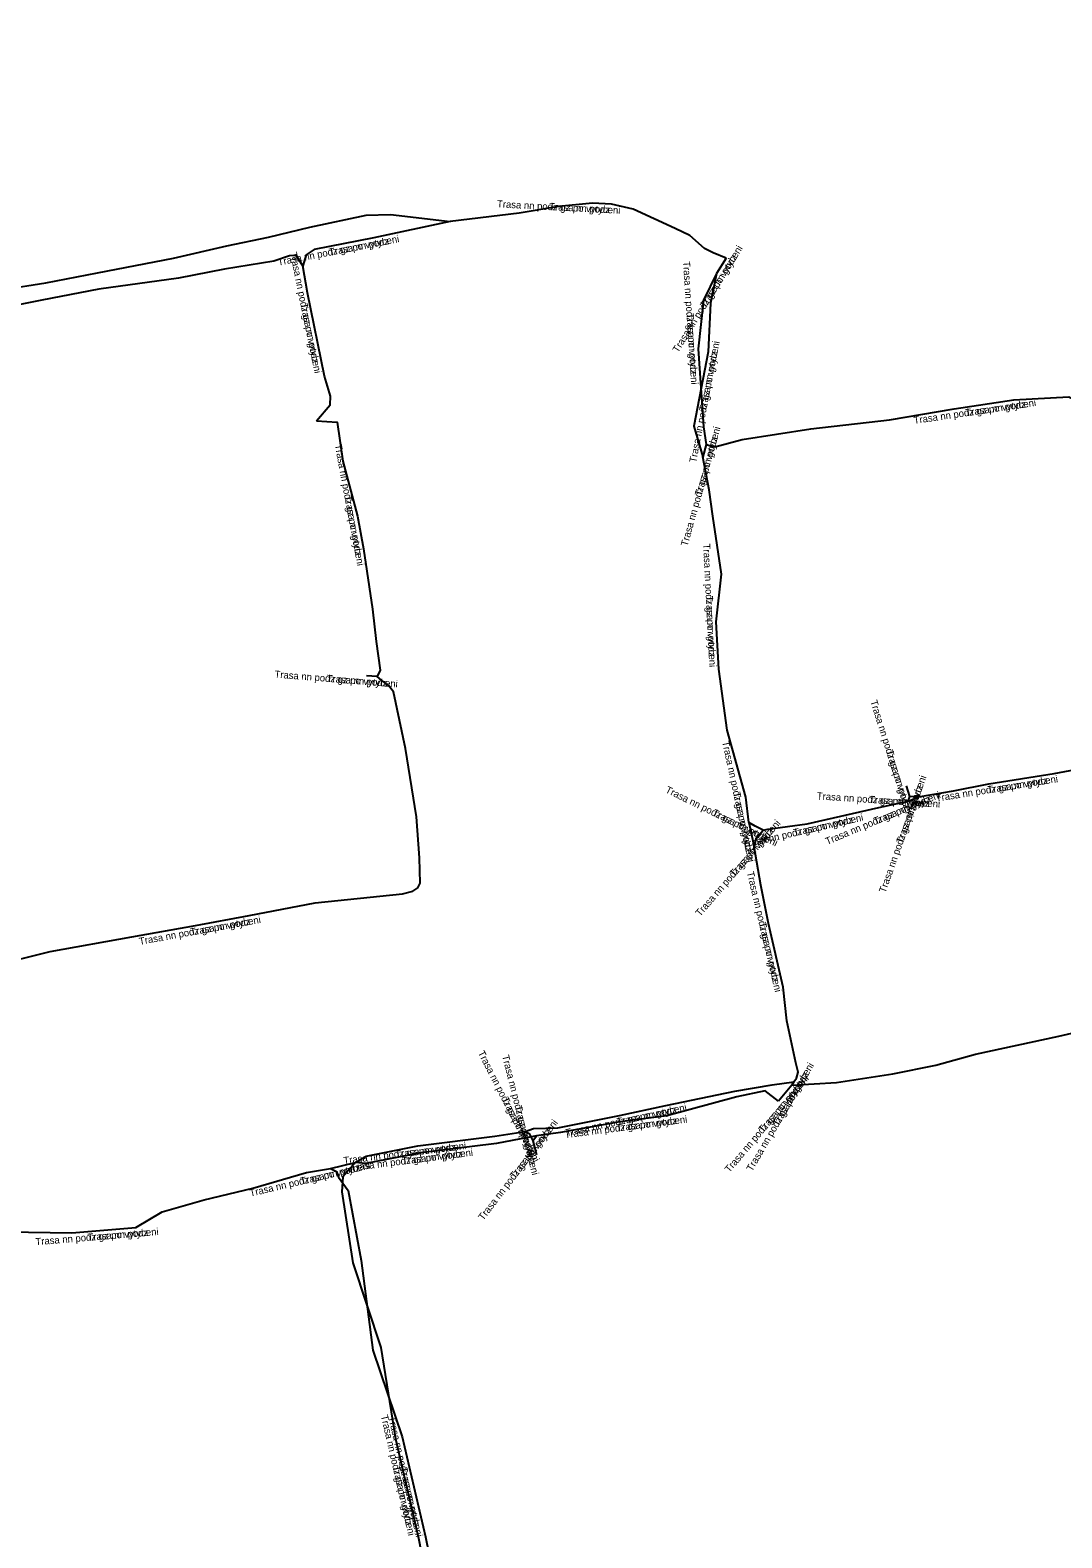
# Model space of a CAD drawing. Extents: x -876384 to -875659, y -1020218 to -1019588.
# Drawn here: x -876029.1 to -875956.5, y -1020036.5 to -1019930.4 of the extents above; entities that cross this region are included whole.
import ezdxf

# ---------------------------------------------------------------- set-up
doc = ezdxf.new("R2010")
doc.units = 0
doc.layers.add('Popiskový text - Ostatní atributy Trasy', color=7, linetype='Continuous')
doc.layers.add('Spojnice NN', color=7, linetype='Continuous')

msp = doc.modelspace()

# ---------------------------------------------------------------- linework, layer by layer
at = {"layer": 'Spojnice NN'}
for points in [[(-876046.32, -1019930.37), (-876047.08, -1019930.93), (-876047.26, -1019931.59), (-876046.92, -1019933.56), (-876045.88, -1019938.99), (-876044.61, -1019943.83), (-876044.42, -1019946.2), (-876043.76, -1019948.18), (-876043.34, -1019949.51), (-876043.03, -1019949.85), (-876042.41, -1019950.34), (-876039.62, -1019949.85), (-876034.17, -1019949.16), (-876030.99, -1019948.63), (-876028.02, -1019948.16), (-876024.37, -1019947.45), (-876019.01, -1019946.41), (-876015.26, -1019945.54), (-876012.33, -1019944.94), (-876009.41, -1019944.24), (-876005.45, -1019943.4), (-876003.75, -1019943.35), (-875999.53, -1019943.84)], [(-876046.32, -1019930.37), (-876047.08, -1019930.93), (-876047.26, -1019931.59), (-876046.92, -1019933.56), (-876045.88, -1019938.99), (-876044.61, -1019943.83), (-876044.42, -1019946.2), (-876043.76, -1019948.18), (-876043.34, -1019949.51), (-876043.03, -1019949.85), (-876042.41, -1019950.34), (-876039.62, -1019949.85), (-876034.17, -1019949.16), (-876030.99, -1019948.63), (-876028.02, -1019948.16), (-876024.37, -1019947.45), (-876019.01, -1019946.41), (-876015.26, -1019945.54), (-876012.33, -1019944.94), (-876009.41, -1019944.24), (-876005.45, -1019943.4), (-876003.75, -1019943.35), (-875999.53, -1019943.84)], [(-875980.11, -1019946.41), (-875981.02, -1019946.05), (-875981.63, -1019945.73), (-875982.67, -1019944.83), (-875983.7, -1019944.32), (-875986.65, -1019942.96), (-875988.18, -1019942.61), (-875989.51, -1019942.54), (-875991.88, -1019942.79), (-875994.69, -1019943.26), (-875999.53, -1019943.84)], [(-875980.11, -1019946.41), (-875981.02, -1019946.05), (-875981.63, -1019945.73), (-875982.67, -1019944.83), (-875983.7, -1019944.32), (-875986.65, -1019942.96), (-875988.18, -1019942.61), (-875989.51, -1019942.54), (-875991.88, -1019942.79), (-875994.69, -1019943.26), (-875999.53, -1019943.84)], [(-875999.53, -1019943.84), (-876004.92, -1019944.98), (-876009.11, -1019945.8), (-876009.67, -1019946.19), (-876009.91, -1019946.97)], [(-875999.53, -1019943.84), (-876004.92, -1019944.98), (-876009.11, -1019945.8), (-876009.67, -1019946.19), (-876009.91, -1019946.97)], [(-876009.91, -1019946.97), (-876010.39, -1019946.23), (-876010.86, -1019946.25), (-876011.96, -1019946.62), (-876015.42, -1019947.19), (-876018.66, -1019947.82), (-876024.27, -1019948.6), (-876028.29, -1019949.37), (-876031.81, -1019950.07), (-876034.22, -1019950.58), (-876039.28, -1019951.74), (-876039.64, -1019952.03), (-876040, -1019952.31), (-876040, -1019952.91), (-876039.65, -1019954.95), (-876038.91, -1019959.38), (-876038.32, -1019963.68), (-876038.31, -1019964.47), (-876038.83, -1019964.88), (-876041.77, -1019965.75), (-876046.71, -1019966.8), (-876049.27, -1019967.19)], [(-876009.91, -1019946.97), (-876010.39, -1019946.23), (-876010.86, -1019946.25), (-876011.96, -1019946.62), (-876015.42, -1019947.19), (-876018.66, -1019947.82), (-876024.27, -1019948.6), (-876028.29, -1019949.37), (-876031.81, -1019950.07), (-876034.22, -1019950.58), (-876039.28, -1019951.74), (-876039.64, -1019952.03), (-876040, -1019952.31), (-876040, -1019952.91), (-876039.65, -1019954.95), (-876038.91, -1019959.38), (-876038.32, -1019963.68), (-876038.31, -1019964.47), (-876038.83, -1019964.88), (-876041.77, -1019965.75), (-876046.71, -1019966.8), (-876049.27, -1019967.19)], [(-876008.96, -1019957.86), (-876007.98, -1019956.75), (-876007.97, -1019956.13), (-876008.39, -1019954.72), (-876009.59, -1019948.87), (-876009.91, -1019946.97)], [(-876008.96, -1019957.86), (-876007.98, -1019956.75), (-876007.97, -1019956.13), (-876008.39, -1019954.72), (-876009.59, -1019948.87), (-876009.91, -1019946.97)], [(-875980.11, -1019946.41), (-875980.79, -1019947.51)], [(-875980.11, -1019946.41), (-875980.79, -1019947.51)], [(-875980.79, -1019947.51), (-875981.2, -1019949.58), (-875981.36, -1019953.02), (-875982.38, -1019958.25), (-875981.74, -1019960.4)], [(-875980.79, -1019947.51), (-875981.2, -1019949.58), (-875981.36, -1019953.02), (-875982.38, -1019958.25), (-875981.74, -1019960.4)], [(-875980.79, -1019947.51), (-875981.7, -1019949.37), (-875982.08, -1019952.81), (-875981.71, -1019958.3), (-875981.5, -1019959.54)], [(-875980.79, -1019947.51), (-875981.7, -1019949.37), (-875982.08, -1019952.81), (-875981.71, -1019958.3), (-875981.5, -1019959.54)], [(-875981.5, -1019959.54), (-875980.91, -1019959.71), (-875978.98, -1019959.19), (-875974.14, -1019958.44), (-875968.61, -1019957.8), (-875964.04, -1019957.02), (-875959.85, -1019956.4), (-875955.98, -1019956.19), (-875954.28, -1019957), (-875950.88, -1019959.65), (-875949.21, -1019960.94), (-875946.66, -1019963.08), (-875946.09, -1019963.7), (-875943.8, -1019965.43), (-875942.97, -1019965.54), (-875941.85, -1019965.97)], [(-875981.5, -1019959.54), (-875980.91, -1019959.71), (-875978.98, -1019959.19), (-875974.14, -1019958.44), (-875968.61, -1019957.8), (-875964.04, -1019957.02), (-875959.85, -1019956.4), (-875955.98, -1019956.19), (-875954.28, -1019957), (-875950.88, -1019959.65), (-875949.21, -1019960.94), (-875946.66, -1019963.08), (-875946.09, -1019963.7), (-875943.8, -1019965.43), (-875942.97, -1019965.54), (-875941.85, -1019965.97)], [(-876008.96, -1019957.86), (-876007.49, -1019957.97), (-876007.09, -1019960.71), (-876006.07, -1019964.57), (-876005.64, -1019966.87), (-876005.01, -1019971.13), (-876004.75, -1019973.39), (-876004.46, -1019975.42), (-876004.68, -1019975.87)], [(-876008.96, -1019957.86), (-876007.49, -1019957.97), (-876007.09, -1019960.71), (-876006.07, -1019964.57), (-876005.64, -1019966.87), (-876005.01, -1019971.13), (-876004.75, -1019973.39), (-876004.46, -1019975.42), (-876004.68, -1019975.87)], [(-875981.5, -1019959.54), (-875981.74, -1019960.4)], [(-875981.5, -1019959.54), (-875981.74, -1019960.4)], [(-875978.5, -1019986.14), (-875978.73, -1019984.36), (-875980.03, -1019979.65), (-875980.63, -1019975.35), (-875980.8, -1019972.01), (-875980.43, -1019968.65), (-875981.04, -1019964.59), (-875981.31, -1019962.72), (-875981.74, -1019960.4)], [(-875978.5, -1019986.14), (-875978.73, -1019984.36), (-875980.03, -1019979.65), (-875980.63, -1019975.35), (-875980.8, -1019972.01), (-875980.43, -1019968.65), (-875981.04, -1019964.59), (-875981.31, -1019962.72), (-875981.74, -1019960.4)], [(-876043.1, -1019998.12), (-876042.68, -1019998.01), (-876040.94, -1019997.81), (-876037.72, -1019997.37), (-876032.34, -1019996.37), (-876027.71, -1019995.21), (-876021.96, -1019994.19), (-876017.47, -1019993.38), (-876013.69, -1019992.69), (-876009.04, -1019991.79), (-876002.9, -1019991.16), (-876002.17, -1019990.97), (-876001.82, -1019990.74), (-876001.65, -1019990.42), (-876001.69, -1019988.63), (-876001.9, -1019985.73), (-876002.68, -1019980.94), (-876003.52, -1019976.94), (-876003.88, -1019976.49), (-876004.36, -1019976.15), (-876004.68, -1019975.87)], [(-876043.1, -1019998.12), (-876042.68, -1019998.01), (-876040.94, -1019997.81), (-876037.72, -1019997.37), (-876032.34, -1019996.37), (-876027.71, -1019995.21), (-876021.96, -1019994.19), (-876017.47, -1019993.38), (-876013.69, -1019992.69), (-876009.04, -1019991.79), (-876002.9, -1019991.16), (-876002.17, -1019990.97), (-876001.82, -1019990.74), (-876001.65, -1019990.42), (-876001.69, -1019988.63), (-876001.9, -1019985.73), (-876002.68, -1019980.94), (-876003.52, -1019976.94), (-876003.88, -1019976.49), (-876004.36, -1019976.15), (-876004.68, -1019975.87)], [(-876004.68, -1019975.87), (-876005.43, -1019975.81)], [(-876004.68, -1019975.87), (-876005.43, -1019975.81)], [(-875966.57, -1019984.34), (-875964.09, -1019983.91), (-875961.6, -1019983.42), (-875957.01, -1019982.68), (-875952.25, -1019981.79), (-875950.75, -1019981.55)], [(-875966.57, -1019984.34), (-875964.09, -1019983.91), (-875961.6, -1019983.42), (-875957.01, -1019982.68), (-875952.25, -1019981.79), (-875950.75, -1019981.55)], [(-875967.17, -1019984.3), (-875967.4, -1019983.57)], [(-875967.17, -1019984.3), (-875967.4, -1019983.57)], [(-875967.29, -1019984.64), (-875967.17, -1019984.3)], [(-875967.29, -1019984.64), (-875967.17, -1019984.3)], [(-875967.29, -1019984.64), (-875966.57, -1019984.34)], [(-875967.29, -1019984.64), (-875966.57, -1019984.34)], [(-875966.57, -1019984.34), (-875967.17, -1019984.3)], [(-875966.57, -1019984.34), (-875967.17, -1019984.3)], [(-875977.5, -1019986.68), (-875977.16, -1019986.62), (-875974.39, -1019986.24), (-875969.36, -1019985.09), (-875967.29, -1019984.64)], [(-875977.5, -1019986.68), (-875977.16, -1019986.62), (-875974.39, -1019986.24), (-875969.36, -1019985.09), (-875967.29, -1019984.64)], [(-875978.5, -1019986.14), (-875978.13, -1019987.86)], [(-875977.5, -1019986.68), (-875978.07, -1019986.4), (-875978.5, -1019986.14)], [(-875978.5, -1019986.14), (-875978.13, -1019987.86)], [(-875977.5, -1019986.68), (-875978.07, -1019986.4), (-875978.5, -1019986.14)], [(-875978.13, -1019987.86), (-875977.96, -1019987.21), (-875977.5, -1019986.68)], [(-875978.13, -1019987.86), (-875977.96, -1019987.21), (-875977.5, -1019986.68)], [(-875975.33, -1020004.39), (-875975.14, -1020004.14), (-875975.03, -1020003.71), (-875975.2, -1020003.05), (-875975.82, -1020000.1), (-875976.08, -1019997.73), (-875977.13, -1019993.26), (-875977.66, -1019990.56), (-875978.13, -1019987.86)], [(-875975.33, -1020004.39), (-875975.14, -1020004.14), (-875975.03, -1020003.71), (-875975.2, -1020003.05), (-875975.82, -1020000.1), (-875976.08, -1019997.73), (-875977.13, -1019993.26), (-875977.66, -1019990.56), (-875978.13, -1019987.86)], [(-875975.47, -1020004.63), (-875972.34, -1020004.43), (-875968.36, -1020003.82), (-875965.34, -1020003.23), (-875962.55, -1020002.44), (-875956.68, -1020001.19), (-875952.92, -1020000.31), (-875949.46, -1019999.58), (-875945.94, -1019998.74), (-875940.82, -1019997.67), (-875936.58, -1019996.62), (-875933.3, -1019996.1), (-875928.99, -1019995.29), (-875926.52, -1019994.63), (-875924.66, -1019994.27), (-875923.64, -1019994.19)], [(-875975.47, -1020004.63), (-875972.34, -1020004.43), (-875968.36, -1020003.82), (-875965.34, -1020003.23), (-875962.55, -1020002.44), (-875956.68, -1020001.19), (-875952.92, -1020000.31), (-875949.46, -1019999.58), (-875945.94, -1019998.74), (-875940.82, -1019997.67), (-875936.58, -1019996.62), (-875933.3, -1019996.1), (-875928.99, -1019995.29), (-875926.52, -1019994.63), (-875924.66, -1019994.27), (-875923.64, -1019994.19)], [(-875994.26, -1020007.89), (-875993.66, -1020007.68), (-875991.95, -1020007.63), (-875987.62, -1020006.77), (-875984.36, -1020006.07), (-875979.49, -1020005.04), (-875976.87, -1020004.6), (-875975.33, -1020004.39)], [(-875994.26, -1020007.89), (-875993.66, -1020007.68), (-875991.95, -1020007.63), (-875987.62, -1020006.77), (-875984.36, -1020006.07), (-875979.49, -1020005.04), (-875976.87, -1020004.6), (-875975.33, -1020004.39)], [(-875975.47, -1020004.63), (-875976.42, -1020005.75)], [(-875975.47, -1020004.63), (-875976.42, -1020005.75)], [(-875975.33, -1020004.39), (-875975.47, -1020004.63)], [(-875975.33, -1020004.39), (-875975.47, -1020004.63)], [(-875976.42, -1020005.75), (-875977.36, -1020005.03), (-875979.35, -1020005.46), (-875984.27, -1020006.79), (-875987.58, -1020007.21), (-875991.78, -1020007.95), (-875993.45, -1020008.2)], [(-875976.42, -1020005.75), (-875977.36, -1020005.03), (-875979.35, -1020005.46), (-875984.27, -1020006.79), (-875987.58, -1020007.21), (-875991.78, -1020007.95), (-875993.45, -1020008.2)], [(-876006.23, -1020010.08), (-876005.46, -1020009.62), (-876001.82, -1020008.89), (-875996.4, -1020008.22), (-875994.26, -1020007.89)], [(-876006.23, -1020010.08), (-876005.46, -1020009.62), (-876001.82, -1020008.89), (-875996.4, -1020008.22), (-875994.26, -1020007.89)], [(-875994.26, -1020007.89), (-875993.97, -1020008.03), (-875993.71, -1020008.54)], [(-875994.26, -1020007.89), (-875993.97, -1020008.03), (-875993.71, -1020008.54)], [(-875993.45, -1020008.2), (-875996.28, -1020008.73), (-876001.6, -1020009.4), (-876005.47, -1020010.15), (-876006.23, -1020010.08)], [(-875993.45, -1020008.2), (-875996.28, -1020008.73), (-876001.6, -1020009.4), (-876005.47, -1020010.15), (-876006.23, -1020010.08)], [(-875993.71, -1020008.54), (-875993.45, -1020008.2)], [(-875993.71, -1020008.54), (-875993.45, -1020008.2)], [(-875993.71, -1020008.54), (-875993.46, -1020009.53)], [(-875993.71, -1020008.54), (-875993.46, -1020009.53)], [(-876036.57, -1020015.08), (-876033.62, -1020014.51), (-876030.75, -1020014.95), (-876026.19, -1020015.03), (-876021.67, -1020014.65), (-876019.83, -1020013.55), (-876016.85, -1020012.7), (-876013.43, -1020011.88), (-876009.66, -1020010.77), (-876007.97, -1020010.49)], [(-876036.57, -1020015.08), (-876033.62, -1020014.51), (-876030.75, -1020014.95), (-876026.19, -1020015.03), (-876021.67, -1020014.65), (-876019.83, -1020013.55), (-876016.85, -1020012.7), (-876013.43, -1020011.88), (-876009.66, -1020010.77), (-876007.97, -1020010.49)], [(-876007.97, -1020010.49), (-876006.23, -1020010.08)], [(-876007.97, -1020010.49), (-876006.23, -1020010.08)], [(-876007.97, -1020010.49), (-876007.54, -1020010.71), (-876007.4, -1020011.1), (-876006.73, -1020012.04), (-876005.81, -1020016.98), (-876004.99, -1020023.28), (-876002.91, -1020029.39), (-876001.28, -1020036.42), (-876000.18, -1020041.82), (-875999.24, -1020046.07), (-875998.13, -1020052.62), (-875996.48, -1020058.31), (-875996.81, -1020058.98)], [(-876007.97, -1020010.49), (-876007.54, -1020010.71), (-876007.4, -1020011.1), (-876006.73, -1020012.04), (-876005.81, -1020016.98), (-876004.99, -1020023.28), (-876002.91, -1020029.39), (-876001.28, -1020036.42), (-876000.18, -1020041.82), (-875999.24, -1020046.07), (-875998.13, -1020052.62), (-875996.48, -1020058.31), (-875996.81, -1020058.98)], [(-876006.23, -1020010.08), (-876006.58, -1020010.47), (-876007.09, -1020011.09), (-876007.16, -1020012.14), (-876006.39, -1020017.14), (-876004.42, -1020023.09), (-876003.38, -1020029.52), (-876001.78, -1020036.52), (-876000.71, -1020041.94), (-875999.84, -1020046.22), (-875997.71, -1020052.52), (-875997.02, -1020058.35), (-875996.81, -1020058.98)], [(-876006.23, -1020010.08), (-876006.58, -1020010.47), (-876007.09, -1020011.09), (-876007.16, -1020012.14), (-876006.39, -1020017.14), (-876004.42, -1020023.09), (-876003.38, -1020029.52), (-876001.78, -1020036.52), (-876000.71, -1020041.94), (-875999.84, -1020046.22), (-875997.71, -1020052.52), (-875997.02, -1020058.35), (-875996.81, -1020058.98)]]:
    msp.add_lwpolyline(points, dxfattribs=at)

# ---------------------------------------------------------------- texts
at = {"layer": 'Popiskový text - Ostatní atributy Trasy'}
for s, rotation, p in [('Trasa nn podz gz po vytyceni', 356.9872, (-875996.25, -1019942.84)), ('Trasa nn podz', 356.9872, (-875992.57, -1019943.03)), ('Trasa nn podz gz po vytyceni', 11.0731, (-876011.63, -1019946.95)), ('Trasa nn podz', 11.0731, (-876008.01, -1019946.25)), ('Trasa nn podz gz po vytyceni', 281.5922, (-876010.83, -1019946.04)), ('Trasa nn podz gz po vytyceni', 58.2764, (-875983.49, -1019953.11)), ('Trasa nn podz', 58.2764, (-875981.55, -1019949.98)), ('Trasa nn podz gz po vytyceni', 273.8556, (-875983.15, -1019946.65)), ('Trasa nn podz', 281.5922, (-876010.09, -1019949.65)), ('Trasa nn podz', 273.8556, (-875982.9, -1019950.33)), ('Trasa nn podz gz po vytyceni', 78.9642, (-875982.22, -1019960.84)), ('Trasa nn podz', 78.9642, (-875981.52, -1019957.22)), ('Trasa nn podz gz po vytyceni', 8.4171, (-875966.86, -1019958.09)), ('Trasa nn podz', 8.4171, (-875963.21, -1019957.55)), ('Trasa nn podz gz po vytyceni', 74.4072, (-875982.83, -1019966.73)), ('Trasa nn podz', 74.4072, (-875981.84, -1019963.18)), ('Trasa nn podz gz po vytyceni', 280.5896, (-876007.67, -1019959.56)), ('Trasa nn podz', 280.5896, (-876006.99, -1019963.19)), ('Trasa nn podz gz po vytyceni', 272.9137, (-875981.73, -1019966.53)), ('Trasa nn podz', 272.9137, (-875981.54, -1019970.21)), ('Trasa nn podz gz po vytyceni', 355.4261, (-876011.92, -1019975.94)), ('Trasa nn podz', 355.4261, (-876008.24, -1019976.24)), ('Trasa nn podz gz po vytyceni', 287.488, (-875969.96, -1019977.61)), ('Trasa nn podz gz po vytyceni', 282.1402, (-875980.39, -1019980.46)), ('Trasa nn podz', 287.488, (-875968.85, -1019981.13)), ('Trasa nn podz gz po vytyceni', 70.56, (-875968.89, -1019991.13)), ('Trasa nn podz gz po vytyceni', 9.1584, (-875965.3, -1019984.68)), ('Trasa nn podz', 9.1584, (-875961.66, -1019984.09)), ('Trasa nn podz gz po vytyceni', 333.8384, (-875984.43, -1019984)), ('Trasa nn podz', 282.1402, (-875979.61, -1019984.06)), ('Trasa nn podz gz po vytyceni', 356.1859, (-875973.73, -1019984.51)), ('Trasa nn podz gz po vytyceni', 22.6199, (-875972.99, -1019987.72)), ('Trasa nn podz', 356.1859, (-875970.05, -1019984.76)), ('Trasa nn podz', 22.6199, (-875969.59, -1019986.3)), ('Trasa nn podz', 70.56, (-875967.66, -1019987.65)), ('Trasa nn podz', 333.8384, (-875981.12, -1019985.62)), ('Trasa nn podz gz po vytyceni', 12.8781, (-875978.89, -1019987.94)), ('Trasa nn podz gz po vytyceni', 49.0445, (-875981.94, -1019992.79)), ('Trasa nn podz', 49.0445, (-875979.52, -1019990)), ('Trasa nn podz', 12.8781, (-875975.3, -1019987.11)), ('Trasa nn podz gz po vytyceni', 283.2191, (-875978.65, -1019989.65)), ('Trasa nn podz gz po vytyceni', 10.3449, (-876021.4, -1019994.76)), ('Trasa nn podz', 10.3449, (-876017.78, -1019994.1)), ('Trasa nn podz', 283.2191, (-875977.8, -1019993.23)), ('Trasa nn podz gz po vytyceni', 297.0127, (-875997.6, -1020002.35)), ('Trasa nn podz gz po vytyceni', 284.1723, (-875995.89, -1020002.57)), ('Trasa nn podz gz po vytyceni', 59.7436, (-875978.28, -1020010.74)), ('Trasa nn podz gz po vytyceni', 49.6949, (-875979.87, -1020010.82)), ('Trasa nn podz', 49.6949, (-875977.49, -1020008.01)), ('Trasa nn podz', 59.7436, (-875976.42, -1020007.56)), ('Trasa nn podz', 297.0127, (-875995.92, -1020005.63)), ('Trasa nn podz', 284.1723, (-875994.99, -1020006.14)), ('Trasa nn podz gz po vytyceni', 7.2315, (-875991.45, -1020008.36)), ('Trasa nn podz gz po vytyceni', 12.1188, (-875991.35, -1020008.23)), ('Trasa nn podz', 12.1188, (-875987.74, -1020007.46)), ('Trasa nn podz gz po vytyceni', 52.5946, (-875997.21, -1020014.19)), ('Trasa nn podz', 52.5946, (-875994.98, -1020011.27)), ('Trasa nn podz', 7.2315, (-875987.79, -1020007.89)), ('Trasa nn podz gz po vytyceni', 7.0469, (-876007.02, -1020010.19)), ('Trasa nn podz', 7.0469, (-876003.37, -1020009.74)), ('Trasa nn podz gz po vytyceni', 13.2589, (-876013.6, -1020012.48)), ('Trasa nn podz gz po vytyceni', 7.178, (-876006.54, -1020010.68)), ('Trasa nn podz', 7.178, (-876002.89, -1020010.22)), ('Trasa nn podz', 13.2589, (-876010.01, -1020011.64)), ('Trasa nn podz gz po vytyceni', 4.8056, (-876028.72, -1020015.9)), ('Trasa nn podz', 4.8056, (-876025.05, -1020015.59)), ('Trasa nn podz gz po vytyceni', 282.875, (-876004.42, -1020027.9)), ('Trasa nn podz gz po vytyceni', 283.0541, (-876003.9, -1020028)), ('Trasa nn podz', 282.875, (-876003.6, -1020031.49)), ('Trasa nn podz', 283.0541, (-876003.07, -1020031.59))]:
    msp.add_text(s, height=0.5, rotation=rotation, dxfattribs=at).set_placement(p)

doc.saveas('drawing.dxf')
